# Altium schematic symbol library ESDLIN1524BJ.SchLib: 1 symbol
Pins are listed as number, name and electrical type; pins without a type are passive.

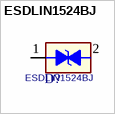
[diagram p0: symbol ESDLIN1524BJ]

## ESDLIN1524BJ
designator D?
footprint ST_SOD323
pins: 1, 2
